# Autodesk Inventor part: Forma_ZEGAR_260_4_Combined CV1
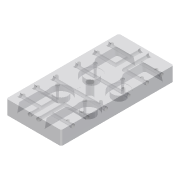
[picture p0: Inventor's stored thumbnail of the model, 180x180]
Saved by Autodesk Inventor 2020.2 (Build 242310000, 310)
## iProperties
Created: 2015-01
Part Number: Forma_ZEGAR_260_4_Combined CV1
Material: Ogólny
Document SubType Name: Modeling
Designer: F.Stasiak
Density: 1 g/cm^3
Appearance: Domyślna
Catalog Web Link: www.expertbooks.pl
Manager: www.cadconsulting.pl
Company: Fabian Stasiak CAD Consulting
Author: F.Stasiak
Subject: Zbiór ćwiczeń. Autodesk Inventor 2020. Kurs Professional
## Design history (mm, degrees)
node "Forma_ZEGAR_260_4_AsmContainer" dims "d0" = 10
sketch "Szkic1"
  geometry: L1 (-78, 160)-(78, 160) reference; L2 (78, 160)-(78, -160) reference; L3 (78, -160)-(-78, -160) reference; L4 (-78, -160)-(-78, 160) reference; L5 (-78, 160)-(78, 160) reference; L6 (78, 160)-(78, -160) reference; L7 (78, -160)-(-78, -160) reference; L8 (-78, -160)-(-78, 160) reference; L9 (-78, 160)-(78, 160) reference; L10 (78, 160)-(78, -160) reference; L11 (78, -160)-(-78, -160) reference; L12 (-78, -160)-(-78, 160) reference; L13 (-78, 160)-(78, 160) reference; L14 (78, 160)-(78, -160) reference; L15 (78, -160)-(-78, -160) reference; L16 (-78, -160)-(-78, 160) reference; L17 (-78, 160)-(78, 160); L18 (78, 160)-(78, -160); L19 (78, -160)-(-78, -160); L20 (-78, -160)-(-78, 160)
  constraints: 8 end point, 2 parallel, 1 horizontal, 1 perpendicular
sketch "Szkic2"
  geometry: L1 (-78, 160)-(78, 160) reference; L2 (78, 160)-(78, -160) reference; L3 (78, -160)-(-78, -160) reference; L4 (-78, -160)-(-78, 160) reference
sketch "Szkic3"
  geometry: L1 (-78, 160)-(78, 160) reference; L2 (78, 160)-(78, -160) reference; L3 (78, -160)-(-78, -160) reference; L4 (-78, -160)-(-78, 160) reference
sketch "Szkic4"
  geometry: L1 (-78, 160)-(78, 160) reference; L2 (78, 160)-(78, -160) reference; L3 (78, -160)-(-78, -160) reference; L4 (-78, -160)-(-78, 160) reference
sketch "Szkic5"
  geometry: L1 (-78, 160)-(78, 160) reference; L2 (78, 160)-(78, -160) reference; L3 (78, -160)-(-78, -160) reference; L4 (-78, -160)-(-78, 160) reference
chamfer "Faza1" distance "d1" = 3; stored, may be unused: second distance "d2" = 3, angle "d3" = 45 deg
chamfer "Faza2" distance "d4" = 3; stored, may be unused: second distance "d5" = 3, angle "d6" = 45 deg
chamfer "Faza3" distance "d7" = 3; stored, may be unused: second distance "d8" = 3, angle "d9" = 45 deg
chamfer "Faza4" distance "d10" = 3; stored, may be unused: second distance "d11" = 3, angle "d12" = 45 deg
feature "Rzeźbienie2"
feature "Gwint1" dims "d13" = 0, "d14" = 0
feature "Rzeźbienie3"
feature "Gwint2" dims "d15" = 0, "d16" = 0
feature "Rzeźbienie4"
feature "Rzeźbienie5"
feature "Gwint3" dims "d17" = 0, "d18" = 0
feature "Rzeźbienie6"
feature "Gwint4" dims "d19" = 0, "d20" = 0
feature "Rzeźbienie7"
feature "Rzeźbienie8"
feature "Gwint5" dims "d21" = 0, "d22" = 0
feature "Rzeźbienie9"
feature "Gwint6" dims "d23" = 0, "d24" = 0
feature "Rzeźbienie10"
feature "Gwint7" dims "d25" = 0, "d26" = 0
feature "Rzeźbienie11"
feature "Gwint8" dims "d27" = 0, "d28" = 0
feature "Rzeźbienie12"
feature "Rzeźbienie13"
feature "Rzeźbienie14"
feature "Rzeźbienie15"
node "Bryła1"
node "Forma_ZEGAR_260_4_ZEGAR_260_CV_1:1" dims "d0" = 10
node "Forma_ZEGAR_260_4_ZEGAR_260_CV_2:1" dims "d0" = 10
node "Forma_ZEGAR_260_4_ZEGAR_260_CV_3:1" dims "d0" = 10
node "Forma_ZEGAR_260_4_ZEGAR_260_CV_4:1" dims "d0" = 10
feature "Powierzchnia2"
body "Srf2"
feature "Powierzchnia3"
body "Srf3"
feature "Powierzchnia4"
body "Srf4"
feature "Powierzchnia5"
body "Srf5"
feature "Powierzchnia6"
body "Srf6"
feature "Powierzchnia7"
body "Srf7"
feature "Powierzchnia8"
body "Srf8"
feature "Powierzchnia9"
body "Srf9"
feature "Powierzchnia10"
body "Srf10"
feature "Powierzchnia11"
body "Srf11"
feature "Powierzchnia12"
body "Srf12"
feature "Powierzchnia13"
body "Srf13"
feature "Powierzchnia14"
body "Srf14"
feature "Powierzchnia15"
body "Srf15"
